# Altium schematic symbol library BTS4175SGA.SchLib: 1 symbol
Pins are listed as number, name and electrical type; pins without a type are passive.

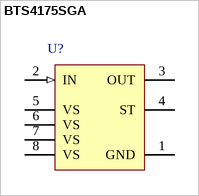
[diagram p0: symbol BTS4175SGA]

## BTS4175SGA
designator U?
Smart High-Side Power Switch, 1 Channel, 1.3 A Load Current, -40 to 150 degC, PG-DSO-8-24, Reel, Green; Manufacturer: Infineon; PartNumber: BTS4175SGA; Channels: 1; Green: TRUE; Group: Automotive Qualified; Load Current (typ): 1.3 A; Ptot (max): 1.5 W; Recommended Operating Voltage Max.: 52 V; Recommended Operating Voltage Min.: 6 V; RON @ 25degreesC: 175 mOhm; RON(max) @ 150degreesC: 350 mOhm; toff (max): 200 us; ton (max): 180 us
footprint INF-PG-DSO-8-24_N (SOP, 8-Leads, Body 4.9x3.9mm, Pitch 1.27mm, IPC Medium Density)
footprint INF-PG-DSO-8-24_L (SOP, 8-Leads, Body 4.9x3.9mm, Pitch 1.27mm, IPC High Density)
footprint INF-PG-DSO-8-24_M (SOP, 8-Leads, Body 4.9x3.9mm, Pitch 1.27mm, IPC Low Density)
pins: 1 GND (power) "Ground; Ground connection", 2 IN (in) "Input channel; Input signal. Activate the channel in case of logic high level", 3 OUT (power) "Output; Protected High side power output channel", 4 ST (oc) "Diagnostic feedback; of channel. Open drain.", 5 VS (power) "Battery voltage; Design the wiring for the simultaneous max. short circuit current and also for low thermal resistance", 6 VS (power) "Battery voltage; Design the wiring for the simultaneous max. short circuit current and also for low thermal resistance", 7 VS (power) "Battery voltage; Design the wiring for the simultaneous max. short circuit current and also for low thermal resistance", 8 VS (power) "Battery voltage; Design the wiring for the simultaneous max. short circuit current and also for low thermal resistance"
